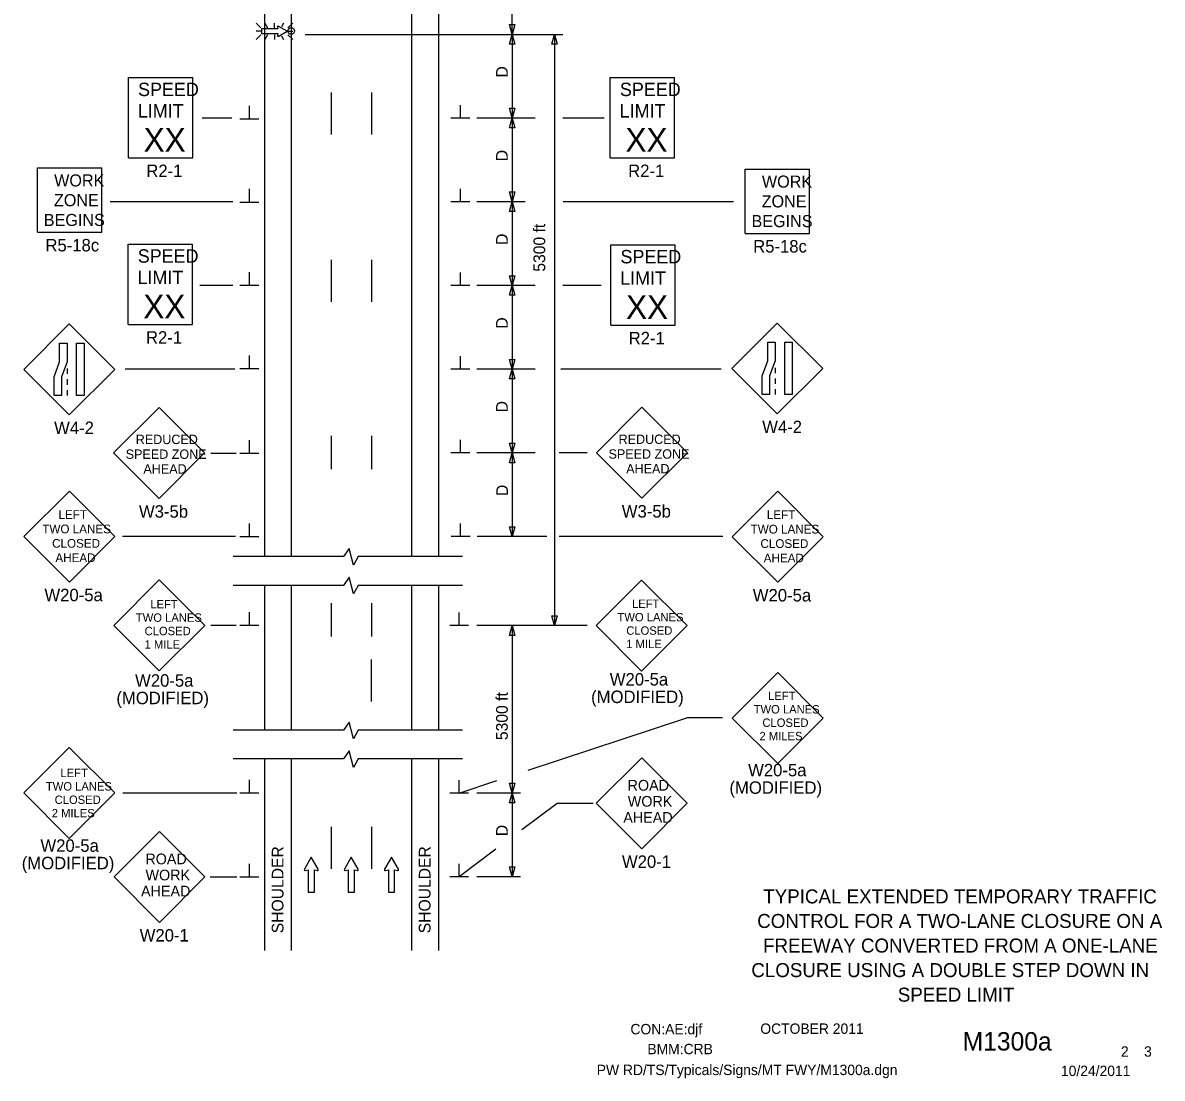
# Model space of a CAD drawing. Extents: x 16590 to 19508, y 5703 to 6974.
# Drawn here: x 17757 to 18437, y 5932 to 6562 of the extents above; entities that cross this region are included whole.
import ezdxf

# ---------------------------------------------------------------- set-up
doc = ezdxf.new("R2010")
doc.units = 0
for name, color, linetype in [('ALI_LEGAL_EX', 7, 'Continuous'), ('BORDER', 7, 'Continuous'), ('BORDER_SIGNAL_WO', 7, 'Continuous'), ('MT_SCRATCH_LEVEL_E', 7, 'Continuous'), ('PAVT_EDGE_EX', 7, 'Continuous'), ('TRAFFIC_SIGNS_PR', 7, 'Continuous'), ('TYPICAL_TEXT_DIMEN_PR', 7, 'Continuous')]:
    doc.layers.add(name, color=color, linetype=linetype)

msp = doc.modelspace()

# ---------------------------------------------------------------- linework, layer by layer
at = {"layer": 'ALI_LEGAL_EX'}
for points in [[(17940.96, 6520.69), (17940.96, 6495.69)], [(17964.96, 6520.69), (17964.96, 6495.69)], [(17940.96, 6420.69), (17940.96, 6395.69)], [(17964.96, 6420.69), (17964.96, 6395.69)], [(17940.96, 6315.64), (17940.96, 6295.69)], [(17964.96, 6315.64), (17964.96, 6295.69)], [(17940.96, 6215.64), (17940.96, 6195.69)], [(17964.96, 6215.64), (17964.96, 6195.69)], [(17964.96, 6156.97), (17964.96, 6181.97)], [(17940.96, 6081.97), (17940.96, 6056.97)], [(17964.96, 6081.97), (17964.96, 6056.97)]]:
    msp.add_lwpolyline(points, dxfattribs=at)
at = {"layer": 'MT_SCRATCH_LEVEL_E'}
for p, q in [((17928.96, 6063.87), (17924.85, 6056.63)), ((17933.1, 6056.63), (17928.96, 6063.87)), ((17952.86, 6063.87), (17948.75, 6056.63)), ((17957.01, 6056.63), (17952.86, 6063.87)), ((17976.91, 6063.87), (17972.8, 6056.63)), ((17981.06, 6056.63), (17976.91, 6063.87)), ((17925.33, 6055.95), (17927.1, 6056.26)), ((17927.1, 6056.26), (17927.1, 6043.01)), ((17930.85, 6043.01), (17930.85, 6056.26)), ((17930.85, 6056.26), (17932.62, 6055.95)), ((17949.23, 6055.95), (17951.01, 6056.26)), ((17951.01, 6056.26), (17951.01, 6043.01)), ((17954.75, 6043.01), (17954.75, 6056.26)), ((17954.75, 6056.26), (17956.53, 6055.95)), ((17973.28, 6055.95), (17975.06, 6056.26)), ((17975.06, 6056.26), (17975.06, 6043.01)), ((17978.8, 6043.01), (17978.8, 6056.26)), ((17978.8, 6056.26), (17980.58, 6055.95)), ((17927.1, 6043.01), (17930.85, 6043.01)), ((17951.01, 6043.01), (17954.75, 6043.01)), ((17975.06, 6043.01), (17978.8, 6043.01))]:
    msp.add_line(p, q, dxfattribs=at)
for centre, start, end in [((17925.25, 6056.41), 150.42484, 279.96381), ((17932.69, 6056.41), 260.03619, 29.77312), ((17949.16, 6056.41), 150.42484, 279.96381), ((17956.6, 6056.41), 260.03619, 29.77312), ((17973.21, 6056.41), 150.42484, 279.96381), ((17980.65, 6056.41), 260.03619, 29.77312)]:
    msp.add_arc(centre, 0.463, start, end, dxfattribs=at)
at = {"layer": 'PAVT_EDGE_EX'}
for p, q in [((17900.96, 6925.33), (17900.96, 6243.41)), ((17916.96, 6925.33), (17916.96, 6243.41)), ((17988.96, 6925.33), (17988.96, 6243.41)), ((18004.96, 6925.33), (18004.96, 6243.41)), ((17900.96, 6226.27), (17900.96, 6216.94)), ((17916.96, 6226.27), (17916.96, 6139.78)), ((17988.96, 6226.27), (17988.96, 6139.78)), ((18004.96, 6226.27), (18004.96, 6139.78)), ((17900.96, 6216.94), (17900.96, 6139.77)), ((17988.96, 6218.33), (17988.96, 6216.94)), ((18004.96, 6217.43), (18004.96, 6216.94)), ((17900.96, 6122.63), (17900.96, 6008.06)), ((17916.96, 6122.63), (17916.96, 6008.06)), ((17988.96, 6122.63), (17988.96, 6008.06)), ((18004.96, 6122.63), (18004.96, 6008.06))]:
    msp.add_line(p, q, dxfattribs=at)
at = {"layer": 'TRAFFIC_SIGNS_PR'}
for p, q in [((17898.89, 6559.29), (17896.07, 6562.11)), ((17898.89, 6557.26), (17896.07, 6557.26)), ((17901.19, 6562.11), (17902.82, 6559.29)), ((17906.98, 6559.29), (17906.98, 6562.11)), ((17912.44, 6562.11), (17911.24, 6560.01)), ((17917.88, 6562.11), (17915.06, 6559.29)), ((17915.06, 6557.26), (17917.88, 6557.26)), ((17898.89, 6555.22), (17896.07, 6552.4)), ((17902.84, 6555.22), (17901.21, 6552.4)), ((17906.98, 6555.22), (17906.98, 6552.4)), ((17911.16, 6554.59), (17912.42, 6552.4)), ((17917.88, 6552.4), (17915.06, 6555.22)), ((17819.73, 6529.7), (17858.18, 6529.7)), ((17819.73, 6481.64), (17819.73, 6529.7)), ((17858.18, 6481.64), (17858.18, 6529.7)), ((18107.64, 6529.7), (18146.09, 6529.7)), ((18107.64, 6481.64), (18107.64, 6529.7)), ((18146.09, 6481.64), (18146.09, 6529.7)), ((17819.73, 6481.64), (17858.18, 6481.64)), ((18107.64, 6481.64), (18146.09, 6481.64)), ((17765.36, 6437.21), (17765.36, 6475.61)), ((17765.36, 6475.61), (17803.76, 6475.61)), ((17803.76, 6437.21), (17803.76, 6475.61)), ((18188.23, 6436.53), (18188.23, 6474.93)), ((18188.23, 6474.93), (18226.63, 6474.93)), ((18226.63, 6436.53), (18226.63, 6474.93)), ((17765.36, 6437.21), (17803.76, 6437.21)), ((18188.23, 6436.53), (18226.63, 6436.53)), ((17819.55, 6430.18), (17858, 6430.18)), ((17819.55, 6382.12), (17819.55, 6430.18)), ((17858, 6382.12), (17858, 6430.18)), ((18107.95, 6429.78), (18146.4, 6429.78)), ((18107.95, 6381.72), (18107.95, 6429.78)), ((18146.4, 6381.72), (18146.4, 6429.78)), ((17784.39, 6382.41), (17757.23, 6355.26)), ((17811.54, 6355.26), (17784.39, 6382.41)), ((17819.55, 6382.12), (17858, 6382.12)), ((18107.95, 6381.72), (18146.4, 6381.72)), ((18207.45, 6382.94), (18180.3, 6355.79)), ((18234.61, 6355.79), (18207.45, 6382.94)), ((17757.23, 6355.26), (17784.39, 6328.11)), ((17783.14, 6355.75), (17783.14, 6352.55)), ((17784.39, 6328.11), (17811.54, 6355.26)), ((18180.3, 6355.79), (18207.45, 6328.64)), ((18206.21, 6356.28), (18206.21, 6353.08)), ((18207.45, 6328.64), (18234.61, 6355.79)), ((17783.14, 6349.35), (17783.14, 6346.15)), ((18206.21, 6349.88), (18206.21, 6346.68)), ((17783.14, 6342.95), (17783.14, 6339.75)), ((18206.21, 6343.48), (18206.21, 6340.28)), ((17838.1, 6332.52), (17810.92, 6305.34)), ((17865.29, 6305.34), (17838.1, 6332.52)), ((18126.58, 6332.63), (18099.4, 6305.44)), ((18153.77, 6305.44), (18126.58, 6332.63)), ((17810.92, 6305.34), (17838.1, 6278.15)), ((17838.1, 6278.15), (17865.29, 6305.34)), ((18099.4, 6305.44), (18126.58, 6278.26)), ((18126.58, 6278.26), (18153.77, 6305.44)), ((17784.45, 6282.61), (17757.26, 6255.42)), ((17811.64, 6255.42), (17784.45, 6282.61)), ((18207.67, 6282.48), (18180.48, 6255.29)), ((18234.86, 6255.29), (18207.67, 6282.48)), ((17757.26, 6255.42), (17784.45, 6228.24)), ((17784.45, 6228.24), (17811.64, 6255.42)), ((18180.48, 6255.29), (18207.67, 6228.1)), ((18207.67, 6228.1), (18234.86, 6255.29)), ((17838.14, 6229.53), (17810.96, 6202.34)), ((17865.33, 6202.34), (17838.14, 6229.53)), ((18126.36, 6229.47), (18099.18, 6202.28)), ((18153.55, 6202.28), (18126.36, 6229.47)), ((17810.96, 6202.34), (17838.14, 6175.15)), ((17838.14, 6175.15), (17865.33, 6202.34)), ((18099.18, 6202.28), (18126.36, 6175.1)), ((18126.36, 6175.1), (18153.55, 6202.28)), ((18207.72, 6174.13), (18180.54, 6146.95)), ((18234.91, 6146.95), (18207.72, 6174.13)), ((18180.54, 6146.95), (18207.72, 6119.76)), ((18207.72, 6119.76), (18234.91, 6146.95)), ((17784.41, 6129.44), (17757.22, 6102.25)), ((17811.6, 6102.25), (17784.41, 6129.44)), ((18126.46, 6123.25), (18099.31, 6096.1)), ((18153.62, 6096.1), (18126.46, 6123.25)), ((17757.22, 6102.25), (17784.41, 6075.06)), ((17784.41, 6075.06), (17811.6, 6102.25)), ((18099.31, 6096.1), (18126.46, 6068.94)), ((18126.46, 6068.94), (18153.62, 6096.1)), ((17838.33, 6079.24), (17811.18, 6052.09)), ((17865.48, 6052.09), (17838.33, 6079.24)), ((17811.18, 6052.09), (17838.33, 6024.94)), ((17838.33, 6024.94), (17865.48, 6052.09))]:
    msp.add_line(p, q, dxfattribs=at)
for points in [[(17908.8, 6559.94), (17909.03, 6558.64), (17899.31, 6558.64), (17899.31, 6555.9), (17909.03, 6555.9), (17908.8, 6554.59)], [(17909.3, 6554.24), (17914.61, 6557.26), (17909.3, 6560.3)]]:
    msp.add_lwpolyline(points, dxfattribs=at)
for points in [[(17783.14, 6371), (17783.14, 6359.81), (17779.79, 6350.93), (17779.79, 6339.75), (17775.3, 6339.75), (17775.3, 6350.93), (17778.64, 6359.81), (17778.64, 6371)], [(17793.27, 6371), (17793.27, 6339.75), (17788.78, 6339.75), (17788.78, 6371)], [(18206.21, 6371.53), (18206.21, 6360.34), (18202.86, 6351.46), (18202.86, 6340.28), (18198.37, 6340.28), (18198.37, 6351.46), (18201.71, 6360.34), (18201.71, 6371.53)], [(18216.34, 6371.53), (18216.34, 6340.28), (18211.85, 6340.28), (18211.85, 6371.53)]]:
    msp.add_lwpolyline(points, close=True, dxfattribs=at)
msp.add_circle((17916.97, 6557.46), 2, dxfattribs=at)
for centre, start, end in [((17909.14, 6560), 61.48329, 189.95933), ((17909.14, 6554.54), 170.73078, 298.89165)]:
    msp.add_arc(centre, 0.341, start, end, dxfattribs=at)
at = {"layer": 'TYPICAL_TEXT_DIMEN_PR'}
for p, q in [((18048.96, 6555.41), (18048.96, 6585.97)), ((18048.96, 6555.41), (18047.39, 6561.27)), ((18047.39, 6561.27), (18048.96, 6561.27)), ((18048.96, 6561.27), (18050.53, 6561.27)), ((18050.53, 6561.27), (18048.96, 6555.41)), ((17925.35, 6555.41), (18079.39, 6555.41)), ((17925.35, 6555.41), (18079.39, 6555.41)), ((18047.39, 6549.55), (18048.96, 6555.41)), ((18048.96, 6549.55), (18047.39, 6549.55)), ((18048.96, 6555.41), (18048.96, 6505.41)), ((18048.96, 6555.41), (18050.53, 6549.55)), ((18050.53, 6549.55), (18048.96, 6549.55)), ((18072.82, 6549.55), (18074.39, 6555.41)), ((18074.39, 6549.55), (18072.82, 6549.55)), ((18074.39, 6555.41), (18074.39, 6202.2)), ((18074.39, 6555.41), (18075.96, 6549.55)), ((18075.96, 6549.55), (18074.39, 6549.55)), ((17892.01, 6505.03), (17892.01, 6512.82)), ((18018.08, 6505.41), (18018.08, 6513.19)), ((18048.96, 6505.41), (18047.39, 6511.27)), ((18047.39, 6511.27), (18048.96, 6511.27)), ((18048.96, 6511.27), (18050.53, 6511.27)), ((18050.53, 6511.27), (18048.96, 6505.41)), ((17881.46, 6505.41), (17863.81, 6505.41)), ((17886.38, 6505.03), (17897.63, 6505.03)), ((18023.71, 6505.41), (18012.46, 6505.41)), ((18062.82, 6505.41), (18027.96, 6505.41)), ((18047.39, 6499.55), (18048.96, 6505.41)), ((18048.96, 6505.41), (18048.96, 6455.41)), ((18048.96, 6505.41), (18050.53, 6499.55)), ((18103.99, 6505.41), (18079.39, 6505.41)), ((18048.96, 6499.55), (18047.39, 6499.55)), ((18050.53, 6499.55), (18048.96, 6499.55)), ((17892.01, 6455.27), (17892.01, 6463.06)), ((18018.08, 6455.41), (18018.08, 6463.19)), ((18048.96, 6455.41), (18047.39, 6461.27)), ((18047.39, 6461.27), (18048.96, 6461.27)), ((18048.96, 6461.27), (18050.53, 6461.27)), ((18050.53, 6461.27), (18048.96, 6455.41)), ((17882.14, 6455.41), (17808.81, 6455.41)), ((17886.38, 6455.27), (17897.63, 6455.27)), ((18023.71, 6455.41), (18012.46, 6455.41)), ((18056.71, 6455.41), (18027.96, 6455.41)), ((18047.39, 6449.55), (18048.96, 6455.41)), ((18048.96, 6455.41), (18048.96, 6405.41)), ((18048.96, 6455.41), (18050.53, 6449.55)), ((18181.24, 6455.41), (18079.45, 6455.41)), ((18048.96, 6449.55), (18047.39, 6449.55)), ((18050.53, 6449.55), (18048.96, 6449.55)), ((17892.01, 6405.51), (17892.01, 6413.29)), ((18018.08, 6405.41), (18018.08, 6413.19)), ((18048.96, 6405.41), (18047.39, 6411.27)), ((18047.39, 6411.27), (18048.96, 6411.27)), ((18048.96, 6411.27), (18050.53, 6411.27)), ((18050.53, 6411.27), (18048.96, 6405.41)), ((17882.14, 6405.41), (17862.45, 6405.41)), ((17886.38, 6405.51), (17897.63, 6405.51)), ((18023.71, 6405.41), (18012.46, 6405.41)), ((18062.82, 6405.41), (18027.96, 6405.41)), ((18047.39, 6399.55), (18048.96, 6405.41)), ((18048.96, 6399.55), (18047.39, 6399.55)), ((18048.96, 6405.41), (18048.96, 6355.41)), ((18048.96, 6405.41), (18050.53, 6399.55)), ((18050.53, 6399.55), (18048.96, 6399.55)), ((18102.27, 6405.41), (18079.39, 6405.41)), ((17892.01, 6355.74), (17892.01, 6363.53)), ((18018.08, 6355.41), (18018.08, 6363.19)), ((18048.96, 6355.41), (18047.39, 6361.27)), ((18047.39, 6361.27), (18048.96, 6361.27)), ((18048.96, 6361.27), (18050.53, 6361.27)), ((18050.53, 6361.27), (18048.96, 6355.41)), ((17883.41, 6355.41), (17817.81, 6355.41)), ((17886.38, 6355.74), (17897.63, 6355.74)), ((18023.71, 6355.41), (18012.46, 6355.41)), ((18062.82, 6355.41), (18027.96, 6355.41)), ((18047.39, 6349.55), (18048.96, 6355.41)), ((18048.96, 6355.41), (18048.96, 6305.41)), ((18048.96, 6355.41), (18050.53, 6349.55)), ((18173.96, 6355.41), (18078.14, 6355.41)), ((18048.96, 6349.55), (18047.39, 6349.55)), ((18050.53, 6349.55), (18048.96, 6349.55)), ((17892.01, 6305.2), (17892.01, 6312.99)), ((18018.08, 6305.41), (18018.08, 6313.19)), ((18048.96, 6305.41), (18047.39, 6311.27)), ((18047.39, 6311.27), (18048.96, 6311.27)), ((18048.96, 6311.27), (18050.53, 6311.27)), ((18050.53, 6311.27), (18048.96, 6305.41)), ((17869.08, 6305.2), (17884.02, 6305.2)), ((17886.38, 6305.2), (17897.63, 6305.2)), ((18023.71, 6305.41), (18012.46, 6305.41)), ((18062.82, 6305.41), (18027.96, 6305.41)), ((18047.52, 6299.55), (18049.09, 6305.41)), ((18049.09, 6305.41), (18049.09, 6255.41)), ((18049.09, 6305.41), (18050.66, 6299.55)), ((18093.83, 6305.41), (18077.03, 6305.41)), ((18049.09, 6299.55), (18047.52, 6299.55)), ((18050.66, 6299.55), (18049.09, 6299.55)), ((17892.01, 6255.44), (17892.01, 6263.22)), ((18018.22, 6255.41), (18018.22, 6263.19)), ((18049.09, 6255.41), (18047.52, 6261.27)), ((18047.52, 6261.27), (18049.09, 6261.27)), ((18049.09, 6261.27), (18050.66, 6261.27)), ((18050.66, 6261.27), (18049.09, 6255.41)), ((17883.69, 6255.41), (17816.16, 6255.41)), ((17886.38, 6255.44), (17897.63, 6255.44)), ((18023.84, 6255.41), (18012.59, 6255.41)), ((18069.83, 6255.41), (18028.09, 6255.41)), ((18174.92, 6255.41), (18077.03, 6255.41)), ((17948.31, 6243.41), (17882.36, 6243.41)), ((17951.56, 6248.21), (17948.31, 6243.41)), ((17954.3, 6238.27), (17951.56, 6248.21)), ((17957.05, 6243.41), (17954.3, 6238.27)), ((18019.38, 6243.41), (17957.05, 6243.41)), ((17951.56, 6231.07), (17948.31, 6226.27)), ((17954.3, 6221.13), (17951.56, 6231.07)), ((17948.31, 6226.27), (17882.36, 6226.27)), ((17957.05, 6226.27), (17954.3, 6221.13)), ((18019.38, 6226.27), (17957.05, 6226.27)), ((17892.01, 6202.57), (17892.01, 6210.35)), ((18017.33, 6202.2), (18017.33, 6209.99)), ((17869.08, 6202.57), (17884.02, 6202.57)), ((17886.38, 6202.57), (17897.63, 6202.57)), ((18022.96, 6202.2), (18011.71, 6202.2)), ((18093.79, 6202.2), (18027.96, 6202.2)), ((18047.39, 6196.34), (18048.96, 6202.2)), ((18048.96, 6202.2), (18048.96, 6102.2)), ((18048.96, 6202.2), (18050.53, 6196.34)), ((18074.39, 6202.2), (18072.82, 6208.07)), ((18072.82, 6208.07), (18074.39, 6208.07)), ((18074.39, 6208.07), (18075.97, 6208.07)), ((18075.97, 6208.07), (18074.39, 6202.2)), ((18048.96, 6196.34), (18047.39, 6196.34)), ((18050.53, 6196.34), (18048.96, 6196.34)), ((17951.56, 6144.57), (17948.31, 6139.77)), ((17954.3, 6134.63), (17951.56, 6144.57)), ((18058.55, 6115.83), (18153.3, 6147.15)), ((18174.78, 6147.15), (18153.3, 6147.15)), ((17948.31, 6139.77), (17882.36, 6139.77)), ((17957.05, 6139.77), (17954.3, 6134.63)), ((18019.38, 6139.77), (17957.05, 6139.77)), ((17951.56, 6127.43), (17948.31, 6122.63)), ((17954.3, 6117.49), (17951.56, 6127.43)), ((17948.31, 6122.63), (17882.36, 6122.63)), ((17957.05, 6122.63), (17954.3, 6117.49)), ((18019.38, 6122.63), (17957.05, 6122.63)), ((17892.01, 6102.26), (17892.01, 6110.05)), ((18017.33, 6102.2), (18017.33, 6109.99)), ((18017.33, 6102.21), (18039.9, 6109.66)), ((18048.96, 6102.2), (18047.39, 6108.07)), ((18047.39, 6108.07), (18048.96, 6108.07)), ((18048.96, 6108.07), (18050.53, 6108.07)), ((18050.53, 6108.07), (18048.96, 6102.2)), ((17816.47, 6102.26), (17884.61, 6102.26)), ((17886.38, 6102.26), (17897.63, 6102.26)), ((18022.96, 6102.2), (18011.71, 6102.2)), ((18053.96, 6102.2), (18027.96, 6102.2)), ((18047.39, 6096.34), (18048.96, 6102.2)), ((18048.96, 6102.2), (18048.96, 6052.2)), ((18048.96, 6102.2), (18050.53, 6096.34)), ((18048.96, 6096.34), (18047.39, 6096.34)), ((18050.53, 6096.34), (18048.96, 6096.34)), ((18075.86, 6096), (18054.87, 6080.29)), ((18097.34, 6096), (18075.86, 6096)), ((18039.36, 6068.69), (18017.33, 6052.21)), ((17892.01, 6052.2), (17892.01, 6059.99)), ((18017.33, 6052.2), (18017.33, 6059.99)), ((18048.96, 6052.2), (18047.39, 6058.07)), ((18047.39, 6058.07), (18048.96, 6058.07)), ((18048.96, 6058.07), (18050.53, 6058.07)), ((18050.53, 6058.07), (18048.96, 6052.2)), ((17868.62, 6052.2), (17884.61, 6052.2)), ((17886.38, 6052.2), (17897.63, 6052.2)), ((18022.96, 6052.2), (18011.71, 6052.2)), ((18053.96, 6052.2), (18027.96, 6052.2))]:
    msp.add_line(p, q, dxfattribs=at)

# ---------------------------------------------------------------- texts
at = {"layer": 'BORDER'}
for s, p in [('TYPICAL EXTENDED TEMPORARY TRAFFIC', (18199.06, 6036.26)), ('CONTROL FOR A TWO-LANE CLOSURE ON A', (18195.43, 6021.59)), ('FREEWAY CONVERTED FROM A ONE-LANE ', (18198.93, 6006.91)), ('CLOSURE USING A DOUBLE STEP DOWN IN ', (18191.93, 5992.23)), ('SPEED LIMIT', (18279.43, 5977.56))]:
    msp.add_text(s, height=8.3734, dxfattribs=at).set_placement(p)
at = {"layer": 'BORDER_SIGNAL_WO'}
for s, height, p in [('CON:AE:djf  ', 6.2, (18119.69, 5958.06)), ('    OCTOBER 2011    ', 6.2, (18188.08, 5958.34)), ('    M1300a   ', 11, (18301.86, 5948.38)), ('BMM:CRB   ', 6.2, (18129.81, 5946.17)), (' 2    3 ', 6.2, (18410.45, 5944.7)), ('PW RD/TS/Typicals/Signs/MT FWY/M1300a.dgn      ', 6.2, (18099.55, 5933.71)), ('10/24/2011    ', 6.2, (18376.93, 5933.13))]:
    msp.add_text(s, height=height, dxfattribs=at).set_placement(p)
at = {"layer": 'TRAFFIC_SIGNS_PR'}
for s, height, p in [('SPEED', 8.01, (17825.51, 6518.55)), ('SPEED', 8.01, (18113.41, 6518.55)), ('LIMIT', 8.01, (17825.35, 6505.73)), ('LIMIT', 8.01, (18113.25, 6505.73)), ('XX', 14.048, (17828.86, 6485.4)), ('XX', 14.048, (18116.76, 6485.4)), ('R2-1', 7.449, (17830.43, 6470.19)), ('R2-1', 7.449, (18118.33, 6470.19)), ('WORK', 7.217, (17775.36, 6464.57)), ('WORK', 7.217, (18198.23, 6463.89)), ('ZONE', 7.217, (17775.24, 6452.76)), ('ZONE', 7.217, (18198.11, 6452.08)), ('BEGINS', 7.217, (17769.17, 6440.95)), ('BEGINS', 7.217, (18192.04, 6440.27)), ('R5-18c', 7.44, (17770.17, 6425.77)), ('SPEED', 8.01, (17825.32, 6419.03)), ('SPEED', 8.01, (18113.73, 6418.63)), ('R5-18c', 7.44, (18193.04, 6425.09)), ('LIMIT', 8.01, (17825.16, 6406.21)), ('LIMIT', 8.01, (18113.57, 6405.82)), ('XX', 14.048, (17828.67, 6385.88)), ('XX', 14.048, (18117.08, 6385.49)), ('R2-1', 7.449, (17830.24, 6370.67)), ('R2-1', 7.449, (18118.64, 6370.27)), ('W4-2', 7.44, (18198.41, 6317.2)), ('W4-2', 7.44, (17775.34, 6316.67)), ('REDUCED', 5.607, (17824.14, 6310.65)), ('REDUCED', 5.607, (18112.62, 6310.76)), ('SPEED ZONE', 5.607, (17818.13, 6301.84)), ('SPEED ZONE', 5.607, (18106.61, 6301.95)), ('AHEAD', 5.607, (17828.7, 6293.03)), ('AHEAD', 5.607, (18117.18, 6293.13)), ('LEFT', 5.206, (17777.98, 6265.97)), ('W3-5b', 7.449, (17826.04, 6266.7)), ('W3-5b', 7.449, (18114.52, 6266.8)), ('LEFT', 5.206, (18201.2, 6265.84)), ('TWO LANES', 5.206, (17768.29, 6257.36)), ('TWO LANES', 5.206, (18191.51, 6257.23)), ('CLOSED', 5.206, (17774.15, 6248.75)), ('CLOSED', 5.206, (18197.37, 6248.62)), ('AHEAD', 5.206, (17776.1, 6240.14)), ('AHEAD', 5.206, (18199.32, 6240.01)), ('W20-5a', 7.449, (17769.57, 6216.78)), ('W20-5a', 7.449, (18192.79, 6216.65)), ('LEFT', 5.006, (17832.83, 6212.51)), ('LEFT', 5.006, (18120.61, 6212.78)), ('TWO LANES', 5.006, (17824.18, 6204.5)), ('TWO LANES', 5.006, (18111.95, 6204.77)), ('CLOSED', 5.006, (17829.41, 6196.49)), ('CLOSED', 5.006, (18117.19, 6196.76)), ('1 MILE', 5.006, (17829.4, 6188.49)), ('1 MILE', 5.006, (18117.18, 6188.75)), ('W20-5a', 7.449, (17823.71, 6165.72)), ('W20-5a', 7.449, (18107.35, 6166.42)), ('(MODIFIED)', 7.449, (17812.55, 6155.27)), ('(MODIFIED)', 7.449, (18096.19, 6155.96)), ('LEFT', 5.006, (18201.97, 6157.74)), ('TWO LANES', 5.006, (18193.32, 6149.73)), ('CLOSED', 5.006, (18198.55, 6141.73)), ('2 MILES', 5.006, (18196.8, 6133.72)), ('LEFT', 5.006, (17779.1, 6111.71)), ('W20-5a', 7.449, (18190, 6112.18)), ('TWO LANES', 5.006, (17770.44, 6103.7)), ('ROAD', 6.4, (18118, 6103.63)), ('(MODIFIED)', 7.449, (18178.84, 6101.73)), ('CLOSED', 5.006, (17775.68, 6095.69)), ('WORK', 6.4, (18118.11, 6094.03)), ('2 MILES', 5.006, (17773.93, 6087.68)), ('AHEAD', 6.4, (18115.42, 6084.43)), ('W20-5a', 7.449, (17767.17, 6067.1)), ('ROAD', 6.4, (17829.87, 6059.63)), ('(MODIFIED)', 7.449, (17756.01, 6056.65)), ('W20-1', 7.44, (18114.63, 6057.5)), ('WORK', 6.4, (17829.98, 6050.03)), ('AHEAD', 6.4, (17827.29, 6040.43)), ('W20-1', 7.44, (17826.5, 6013.5))]:
    msp.add_text(s, height=height, dxfattribs=at).set_placement(p)
at = {"layer": 'TYPICAL_TEXT_DIMEN_PR'}
for s, p in [('D', (18046.4, 6529.63)), ('D', (18046.4, 6479.63)), ('5300 ft', (18068.76, 6413.65)), ('D', (18046.4, 6429.63)), ('D', (18046.4, 6379.63)), ('D', (18046.4, 6329.63)), ('D', (18046.54, 6279.63)), ('5300 ft', (18046.4, 6133.81)), ('D', (18046.4, 6076.42)), ('SHOULDER', (17912.38, 6018.42)), ('SHOULDER', (18000.24, 6018.42))]:
    msp.add_text(s, height=7, rotation=90, dxfattribs=at).set_placement(p)

doc.saveas('drawing.dxf')
